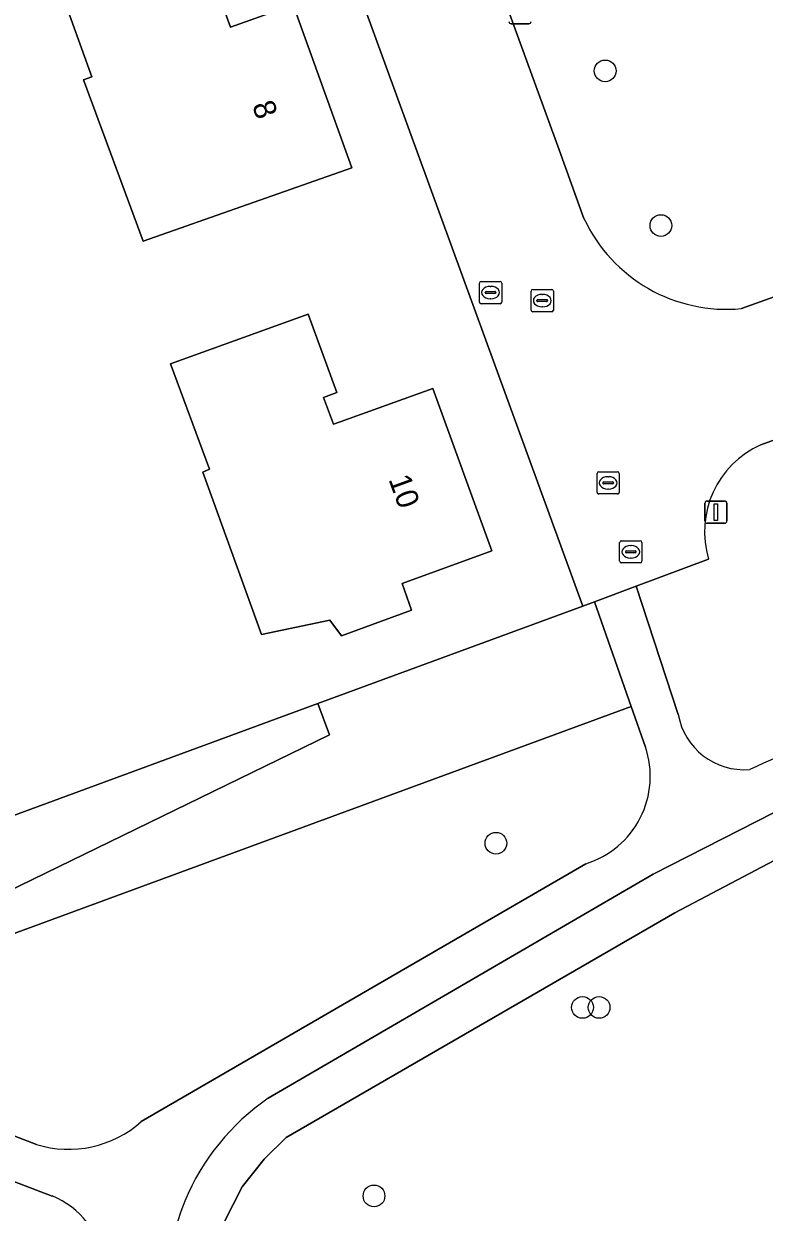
# Model space of a CAD drawing. Extents: x 159499 to 160349, y 382524 to 383273.
# Drawn here: x 159775.1 to 159808.4, y 382799.5 to 382853 of the extents above; entities that cross this region are included whole.
import ezdxf

# ---------------------------------------------------------------- set-up
doc = ezdxf.new("R2010")
doc.units = 0
for name, color, linetype in [('IMGEO_Boom', 7, 'Continuous'), ('IMGEO_Brandkraan', 7, 'Continuous'), ('IMGEO_Erf', 7, 'Continuous'), ('IMGEO_Gemengd_bos', 7, 'Continuous'), ('IMGEO_Groenvoorziening', 7, 'Continuous'), ('IMGEO_Kolk', 7, 'Continuous'), ('IMGEO_Lichtmast', 7, 'Continuous'), ('IMGEO_Pand', 7, 'Continuous'), ('IMGEO_Pand_nummerreeks', 7, 'Continuous'), ('IMGEO_Rijbaan_lokaal_open', 7, 'Continuous'), ('IMGEO_Rioolput', 7, 'Continuous'), ('IMGEO_Voetpad_halfverhard', 7, 'Continuous')]:
    doc.layers.add(name, color=color, linetype=linetype)

msp = doc.modelspace()

# ---------------------------------------------------------------- linework, layer by layer
at = {"layer": 'IMGEO_Boom'}
for centre in [(159801.231, 382850.916), (159803.738, 382843.952), (159796.319, 382816.139), (159800.212, 382808.747), (159800.958, 382808.747), (159790.833, 382800.258)]:
    msp.add_circle(centre, 0.489, dxfattribs=at)
at = {"layer": 'IMGEO_Brandkraan'}
for p, q in [((159795.575, 382840.507), (159795.575, 382841.359)), ((159795.65, 382841.433), (159796.502, 382841.433)), ((159796.576, 382841.359), (159796.576, 382840.507)), ((159795.834, 382840.927), (159795.834, 382840.939)), ((159796.272, 382840.89), (159795.874, 382840.89)), ((159795.877, 382840.976), (159796.275, 382840.976)), ((159796.063, 382841.213), (159796.088, 382841.213)), ((159796.318, 382840.939), (159796.318, 382840.927)), ((159796.502, 382840.433), (159795.65, 382840.433)), ((159796.086, 382840.653), (159796.061, 382840.653))]:
    msp.add_line(p, q, dxfattribs=at)
for points in [[(159795.575, 382840.507), (159795.575, 382841.359)], [(159795.65, 382841.433), (159796.502, 382841.433)], [(159796.576, 382841.359), (159796.576, 382840.507)], [(159796.502, 382840.433), (159795.65, 382840.433)]]:
    msp.add_lwpolyline(points, dxfattribs=at)
for centre, radius, start, end in [((159795.652, 382841.357), 0.0765, 91.552, 178.448), ((159795.652, 382841.357), 0.0765, 91.552, 178.448), ((159796.5, 382841.357), 0.0765, 1.552, 88.448), ((159796.5, 382841.357), 0.0765, 1.552, 88.448), ((159795.874, 382840.936), 0.0403, 85.8775, 175.7526), ((159795.871, 382840.926), 0.0366, 178.938, 274.7102), ((159796.275, 382840.933), 0.043, 264.8664, 352.4533), ((159796.279, 382840.938), 0.0386, 1.7309, 96.639), ((159795.652, 382840.509), 0.0765, 181.552, 268.448), ((159795.652, 382840.509), 0.0765, 181.552, 268.448), ((159796.5, 382840.509), 0.0765, 271.552, 358.448), ((159796.5, 382840.509), 0.0765, 271.552, 358.448)]:
    msp.add_arc(centre, radius, start, end, dxfattribs=at)
for centre, major_axis, ratio, start_param, end_param in [((159796.062, 382840.933), (-0.387, 0.002), 0.722429, 4.712389, 7.853982), ((159796.087, 382840.933), (-0.39, 0.002), 0.717154, 1.570796, 4.712389)]:
    msp.add_ellipse(centre, major_axis=major_axis, ratio=ratio, start_param=start_param, end_param=end_param, dxfattribs=at)
at = {"layer": 'IMGEO_Erf'}
msp.add_lwpolyline([(159797.571, 382912.547), (159772.924, 382944.336), (159765.561, 382953.83), (159760.969, 382951.204), (159750.017, 382945.267), (159739.773, 382940.307), (159729.278, 382935.832), (159728.417, 382938.099), (159719.333, 382934.542), (159720.458, 382931.079), (159730.546, 382899.75), (159741.202, 382899.547), (159744.626, 382889.831), (159753.21, 382866.555), (159754.229, 382863.79), (159753.482, 382863.418), (159757.881, 382849.879), (159758.599, 382850.174), (159770.661, 382815.939), (159788.308, 382822.433), (159800.223, 382826.817), (159778.58, 382886.258)], dxfattribs=at)
for points in [[(159787.196, 382853.887), (159789.832, 382846.551), (159780.443, 382843.243), (159777.762, 382850.507), (159778.141, 382850.641), (159776.283, 382855.821), (159782.488, 382858.042), (159784.384, 382852.878)], [(159789.165, 382836.44), (159788.562, 382836.209), (159789.007, 382835.003), (159789.303, 382835.112), (159793.474, 382836.62), (159796.139, 382829.308), (159792.097, 382827.831), (159792.517, 382826.631), (159789.365, 382825.472), (159788.853, 382826.186), (159785.77, 382825.538), (159783.131, 382832.85), (159783.426, 382832.981), (159781.675, 382837.726), (159787.876, 382839.962)]]:
    msp.add_lwpolyline(points, close=True, dxfattribs=at)
at = {"layer": 'IMGEO_Gemengd_bos'}
msp.add_lwpolyline([(159830.825, 382798.893), (159830.208, 382800.499), (159829.763, 382802.162), (159829.494, 382803.862), (159829.404, 382805.58), (159829.494, 382807.299), (159829.526, 382807.504), (159813.91, 382817.824), (159812.547, 382817.175), (159809.686, 382815.813), (159804.366, 382812.999), (159786.886, 382802.886), (159785.891, 382801.918), (159784.896, 382800.673), (159784.097, 382799.08)], dxfattribs=at)
at = {"layer": 'IMGEO_Groenvoorziening'}
for points in [[(159802.405, 382822.292), (159800.752, 382827.014), (159800.223, 382826.817), (159788.308, 382822.433), (159788.827, 382821.022), (159771.392, 382812.521), (159757.881, 382849.879), (159753.482, 382863.418), (159754.229, 382863.79), (159753.21, 382866.555), (159744.626, 382889.831), (159741.202, 382899.547), (159730.546, 382899.75), (159731.353, 382897.234), (159739.421, 382897.08), (159751.108, 382865.029), (159750.438, 382864.695), (159756.337, 382846.542), (159757.115, 382846.862), (159769.976, 382810.359)], [(159788.308, 382822.433), (159770.661, 382815.939), (159758.599, 382850.174), (159757.881, 382849.879), (159771.392, 382812.521), (159788.827, 382821.022)]]:
    msp.add_lwpolyline(points, close=True, dxfattribs=at)
for points in [[(159803.042, 382820.472), (159802.405, 382822.292), (159769.976, 382810.359), (159757.115, 382846.862), (159756.337, 382846.542), (159750.438, 382864.695), (159751.108, 382865.029), (159739.421, 382897.08), (159731.353, 382897.234), (159732.164, 382894.706), (159737.708, 382895.57), (159759.661, 382827.691), (159765.488, 382806.454), (159767.125, 382805.829), (159767.559, 382806.835), (159774.261, 382804.239), (159773.875, 382803.253), (159775.647, 382802.577)], [(159787.725, 382878.782), (159799.163, 382847.358), (159800.276, 382844.273)], [(159807.364, 382840.209), (159810.087, 382841.188), (159812.324, 382841.966), (159812.286, 382842.137), (159814.174, 382842.897), (159815.07, 382843.33), (159816.499, 382843.734), (159817.98, 382843.831), (159818.72, 382843.763), (159820.159, 382843.398), (159821.491, 382842.742), (159822.098, 382842.314), (159823.162, 382841.278), (159823.929, 382840.666), (159826.17, 382838.606), (159828.184, 382836.324), (159829.948, 382833.844), (159830.767, 382832.194), (159831.478, 382830.305), (159831.989, 382828.352), (159832.292, 382826.356)], [(159829.948, 382833.844), (159828.184, 382836.324), (159826.17, 382838.606), (159823.929, 382840.666), (159823.162, 382841.278), (159822.098, 382842.314), (159821.491, 382842.742), (159820.159, 382843.398), (159818.72, 382843.763), (159817.98, 382843.831), (159816.499, 382843.734), (159815.07, 382843.33), (159814.174, 382842.897), (159812.286, 382842.137), (159812.324, 382841.966), (159814.373, 382836.315), (159808.238, 382834.074)], [(159805.885, 382828.924), (159802.621, 382827.709), (159804.519, 382821.937)], [(159809.686, 382815.813), (159812.547, 382817.175), (159813.91, 382817.824), (159811.957, 382819.109), (159803.394, 382814.748), (159786.077, 382804.655)], [(159781.32, 382792.25), (159781.566, 382785.4), (159782.044, 382778.563), (159783.641, 382765.821), (159784.847, 382758.449), (159786.71, 382759.447), (159785.621, 382766.107), (159784.035, 382778.757), (159783.563, 382785.506), (159783.185, 382794.377), (159783.351, 382796.009), (159783.683, 382797.752), (159784.097, 382799.08), (159784.896, 382800.673), (159785.891, 382801.918), (159786.886, 382802.886), (159804.366, 382812.999), (159809.686, 382815.813)], [(159780.362, 382803.603), (159800.366, 382815.216)], [(159776.356, 382800.255), (159762.472, 382805.567), (159761.59, 382805.778), (159760.683, 382805.736), (159765.523, 382790.674), (159769.997, 382776.771)]]:
    msp.add_lwpolyline(points, dxfattribs=at)
for centre, radius, start, end in [((159806.702, 382847.267), 7.089, 204.984, 275.3592), ((159809.964, 382830.173), 4.266, 113.8643, 197.025), ((159878.907, 382661.215), 173.517, 110.62996, 114.21696), ((159807.474, 382822.45), 2.999, 189.855, 274.9303), ((159799.141, 382819.149), 4.119, 287.2978, 18.738), ((159792.054, 382795.959), 10.552, 124.5022, 157.3473), ((159777.095, 382807.27), 4.911, 252.8545, 311.6982), ((159774.972, 382796.796), 3.726, 7.161, 68.1959), ((159798.565, 382793.991), 17.333, 159.6327, 185.7636)]:
    msp.add_arc(centre, radius, start, end, dxfattribs=at)
at = {"layer": 'IMGEO_Kolk'}
for p, q in [((159797.901, 382840.145), (159797.901, 382840.997)), ((159797.976, 382841.071), (159798.828, 382841.071)), ((159798.389, 382840.851), (159798.414, 382840.851)), ((159798.902, 382840.997), (159798.902, 382840.145)), ((159798.16, 382840.565), (159798.16, 382840.577)), ((159798.598, 382840.528), (159798.2, 382840.528)), ((159798.203, 382840.614), (159798.601, 382840.614)), ((159798.412, 382840.291), (159798.387, 382840.291)), ((159798.644, 382840.577), (159798.644, 382840.565)), ((159798.828, 382840.071), (159797.976, 382840.071)), ((159800.866, 382831.938), (159800.866, 382832.79)), ((159800.941, 382832.864), (159801.793, 382832.864)), ((159801.867, 382832.79), (159801.867, 382831.938)), ((159801.125, 382832.358), (159801.125, 382832.37)), ((159801.563, 382832.321), (159801.165, 382832.321)), ((159801.168, 382832.407), (159801.566, 382832.407)), ((159801.354, 382832.644), (159801.379, 382832.644)), ((159801.609, 382832.37), (159801.609, 382832.358)), ((159801.793, 382831.864), (159800.941, 382831.864)), ((159801.377, 382832.084), (159801.352, 382832.084))]:
    msp.add_line(p, q, dxfattribs=at)
for points in [[(159797.901, 382840.145), (159797.901, 382840.997)], [(159797.976, 382841.071), (159798.828, 382841.071)], [(159798.902, 382840.997), (159798.902, 382840.145)], [(159798.828, 382840.071), (159797.976, 382840.071)], [(159800.866, 382831.938), (159800.866, 382832.79)], [(159800.941, 382832.864), (159801.793, 382832.864)], [(159801.867, 382832.79), (159801.867, 382831.938)], [(159801.793, 382831.864), (159800.941, 382831.864)]]:
    msp.add_lwpolyline(points, dxfattribs=at)
for centre, radius, start, end in [((159797.978, 382840.995), 0.0765, 91.552, 178.448), ((159797.978, 382840.995), 0.0765, 91.552, 178.448), ((159798.826, 382840.995), 0.0765, 1.552, 88.448), ((159798.826, 382840.995), 0.0765, 1.552, 88.448), ((159798.2, 382840.574), 0.0403, 85.8775, 175.7526), ((159798.197, 382840.564), 0.0366, 178.938, 274.7102), ((159798.601, 382840.571), 0.043, 264.8664, 352.4533), ((159798.605, 382840.576), 0.0386, 1.7309, 96.639), ((159797.978, 382840.147), 0.0765, 181.552, 268.448), ((159797.978, 382840.147), 0.0765, 181.552, 268.448), ((159798.826, 382840.147), 0.0765, 271.552, 358.448), ((159798.826, 382840.147), 0.0765, 271.552, 358.448), ((159800.943, 382832.788), 0.0765, 91.552, 178.448), ((159800.943, 382832.788), 0.0765, 91.552, 178.448), ((159801.791, 382832.788), 0.0765, 1.552, 88.448), ((159801.791, 382832.788), 0.0765, 1.552, 88.448), ((159801.165, 382832.367), 0.0403, 85.8775, 175.7526), ((159801.162, 382832.357), 0.0366, 178.938, 274.7102), ((159801.566, 382832.364), 0.043, 264.8664, 352.4533), ((159801.57, 382832.369), 0.0386, 1.7309, 96.639), ((159800.943, 382831.94), 0.0765, 181.552, 268.448), ((159800.943, 382831.94), 0.0765, 181.552, 268.448), ((159801.791, 382831.94), 0.0765, 271.552, 358.448), ((159801.791, 382831.94), 0.0765, 271.552, 358.448)]:
    msp.add_arc(centre, radius, start, end, dxfattribs=at)
for centre, major_axis, ratio, start_param, end_param in [((159798.388, 382840.571), (-0.387, 0.002), 0.722429, 4.712389, 7.853982), ((159798.413, 382840.571), (-0.39, 0.002), 0.717154, 1.570796, 4.712389), ((159801.353, 382832.364), (-0.387, 0.002), 0.722429, 4.712389, 7.853982), ((159801.378, 382832.364), (-0.39, 0.002), 0.717154, 1.570796, 4.712389)]:
    msp.add_ellipse(centre, major_axis=major_axis, ratio=ratio, start_param=start_param, end_param=end_param, dxfattribs=at)
at = {"layer": 'IMGEO_Lichtmast'}
for p, q in [((159797.795, 382853.036), (159797.005, 382853.036)), ((159797.005, 382853.036), (159797.795, 382853.036)), ((159805.716, 382830.648), (159805.716, 382831.448)), ((159805.716, 382831.448), (159805.716, 382830.648)), ((159805.816, 382831.548), (159806.606, 382831.548)), ((159806.606, 382831.548), (159805.816, 382831.548)), ((159806.706, 382831.448), (159806.706, 382830.648)), ((159806.706, 382830.648), (159806.706, 382831.448)), ((159806.606, 382830.548), (159805.816, 382830.548)), ((159805.816, 382830.548), (159806.606, 382830.548))]:
    msp.add_line(p, q, dxfattribs=at)
msp.add_lwpolyline([(159806.136, 382831.423), (159806.286, 382831.423), (159806.286, 382830.673), (159806.136, 382830.673), (159806.136, 382831.423)], dxfattribs=at)
for centre, start, end in [((159797.005, 382853.136), 180, 270), ((159797.005, 382853.136), 180, 270), ((159797.795, 382853.136), 270, 0), ((159797.795, 382853.136), 270, 0), ((159805.816, 382831.448), 90, 180), ((159805.816, 382831.448), 90, 180), ((159806.606, 382831.448), 0, 90), ((159806.606, 382831.448), 360, 90), ((159805.816, 382830.648), 180, 270), ((159805.816, 382830.648), 180, 270), ((159806.606, 382830.648), 270, 0), ((159806.606, 382830.648), 270, 0)]:
    msp.add_arc(centre, 0.1, start, end, dxfattribs=at)
at = {"layer": 'IMGEO_Pand'}
for points in [[(159780.443, 382843.243), (159789.832, 382846.551), (159787.196, 382853.887), (159784.384, 382852.878), (159782.488, 382858.042), (159776.283, 382855.821), (159778.141, 382850.641), (159777.762, 382850.507)], [(159789.365, 382825.472), (159792.517, 382826.631), (159792.097, 382827.831), (159796.139, 382829.308), (159793.474, 382836.62), (159789.303, 382835.112), (159789.007, 382835.003), (159788.562, 382836.209), (159789.165, 382836.44), (159787.876, 382839.962), (159781.675, 382837.726), (159783.426, 382832.981), (159783.131, 382832.85), (159785.77, 382825.538), (159788.853, 382826.186)]]:
    msp.add_lwpolyline(points, close=True, dxfattribs=at)
at = {"layer": 'IMGEO_Rijbaan_lokaal_open'}
for points in [[(159778.58, 382886.258), (159800.223, 382826.817), (159800.752, 382827.014), (159802.621, 382827.709), (159805.885, 382828.924)], [(159800.276, 382844.273), (159799.163, 382847.358), (159787.725, 382878.782)], [(159808.238, 382834.074), (159814.373, 382836.315), (159812.324, 382841.966), (159810.087, 382841.188), (159807.364, 382840.209)]]:
    msp.add_lwpolyline(points, dxfattribs=at)
for centre, radius, start, end in [((159806.702, 382847.267), 7.089, 204.984, 275.3592), ((159809.964, 382830.173), 4.266, 113.8643, 197.025)]:
    msp.add_arc(centre, radius, start, end, dxfattribs=at)
at = {"layer": 'IMGEO_Rioolput'}
for p, q in [((159801.883, 382828.834), (159801.883, 382829.686)), ((159801.958, 382829.76), (159802.81, 382829.76)), ((159802.371, 382829.54), (159802.396, 382829.54)), ((159802.884, 382829.686), (159802.884, 382828.834)), ((159802.142, 382829.254), (159802.142, 382829.266)), ((159802.58, 382829.217), (159802.182, 382829.217)), ((159802.185, 382829.303), (159802.583, 382829.303)), ((159802.394, 382828.98), (159802.369, 382828.98)), ((159802.626, 382829.266), (159802.626, 382829.254)), ((159802.81, 382828.76), (159801.958, 382828.76))]:
    msp.add_line(p, q, dxfattribs=at)
for points in [[(159801.883, 382828.834), (159801.883, 382829.686)], [(159801.958, 382829.76), (159802.81, 382829.76)], [(159802.884, 382829.686), (159802.884, 382828.834)], [(159802.81, 382828.76), (159801.958, 382828.76)]]:
    msp.add_lwpolyline(points, dxfattribs=at)
for centre, radius, start, end in [((159801.96, 382829.684), 0.0765, 91.552, 178.448), ((159801.96, 382829.684), 0.0765, 91.552, 178.448), ((159802.808, 382829.684), 0.0765, 1.552, 88.448), ((159802.808, 382829.684), 0.0765, 1.552, 88.448), ((159802.182, 382829.263), 0.0403, 85.8775, 175.7526), ((159802.179, 382829.253), 0.0366, 178.938, 274.7102), ((159802.583, 382829.26), 0.043, 264.8664, 352.4533), ((159802.587, 382829.265), 0.0386, 1.7309, 96.639), ((159801.96, 382828.836), 0.0765, 181.552, 268.448), ((159801.96, 382828.836), 0.0765, 181.552, 268.448), ((159802.808, 382828.836), 0.0765, 271.552, 358.448), ((159802.808, 382828.836), 0.0765, 271.552, 358.448)]:
    msp.add_arc(centre, radius, start, end, dxfattribs=at)
for centre, major_axis, ratio, start_param, end_param in [((159802.37, 382829.26), (-0.387, 0.002), 0.722429, 4.712389, 7.853982), ((159802.395, 382829.26), (-0.39, 0.002), 0.717154, 1.570796, 4.712389)]:
    msp.add_ellipse(centre, major_axis=major_axis, ratio=ratio, start_param=start_param, end_param=end_param, dxfattribs=at)
at = {"layer": 'IMGEO_Voetpad_halfverhard'}
for points in [[(159804.519, 382821.937), (159802.621, 382827.709), (159800.752, 382827.014), (159802.405, 382822.292), (159803.042, 382820.472)], [(159786.077, 382804.655), (159803.394, 382814.748), (159811.957, 382819.109), (159813.91, 382817.824), (159829.526, 382807.504), (159855.536, 382790.316), (159857.259, 382791.234), (159858.058, 382791.66), (159831.121, 382809.466), (159829.94, 382810.247), (159826.708, 382812.384), (159816.64, 382819.039), (159814.568, 382820.342)], [(159800.366, 382815.216), (159780.362, 382803.603)], [(159759.612, 382809.126), (159760.145, 382807.41), (159760.683, 382805.736), (159761.59, 382805.778), (159762.472, 382805.567), (159776.356, 382800.255)], [(159775.647, 382802.577), (159773.875, 382803.253), (159767.125, 382805.829), (159765.488, 382806.454), (159761.594, 382807.94)]]:
    msp.add_lwpolyline(points, dxfattribs=at)
for centre, radius, start, end in [((159878.907, 382661.215), 173.517, 110.62996, 114.21696), ((159807.474, 382822.45), 2.999, 189.855, 274.9303), ((159799.141, 382819.149), 4.119, 287.2978, 18.738), ((159792.054, 382795.959), 10.552, 124.5022, 157.3473), ((159777.095, 382807.27), 4.911, 252.8545, 311.6982), ((159774.972, 382796.796), 3.726, 7.161, 68.1959), ((159798.565, 382793.991), 17.333, 159.6327, 185.7636)]:
    msp.add_arc(centre, radius, start, end, dxfattribs=at)

# ---------------------------------------------------------------- texts
at = {"layer": 'IMGEO_Pand_nummerreeks'}
for s, rotation, p in [('8', 289.7646, (159785.336, 382849.365)), ('10', 290.0252, (159791.474, 382832.529))]:
    msp.add_text(s, height=1, rotation=rotation, dxfattribs=at).set_placement(p)

doc.saveas('drawing.dxf')
